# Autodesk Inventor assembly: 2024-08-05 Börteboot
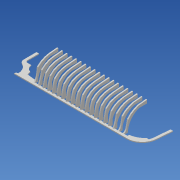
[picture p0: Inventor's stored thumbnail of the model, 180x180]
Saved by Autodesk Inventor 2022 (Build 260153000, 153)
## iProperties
Created: 2024-08
Part Number: 2024-08-05 Börteboot
Document SubType Name: Assembly
Designer: i3meg
Author: i3meg
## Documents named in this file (3)
- E:\Daten Autodesk Inventor 2022\Daten 3D Druck Vorlagen\3D Druck Vorlagen\Modellbau Fahrzeuge Schiffe\U-Boote und Schiffe\Schiffe Volker\Börte Boot\Inventor\2024-08-05 Börteboot 001.iam
- E:\Daten Autodesk Inventor 2022\Daten 3D Druck Vorlagen\3D Druck Vorlagen\Modellbau Fahrzeuge Schiffe\U-Boote und Schiffe\Schiffe Volker\Börte Boot\Inventor\2024-08-05 Börteboot Kiel 001.ipt
- E:\Daten Autodesk Inventor 2022\Daten 3D Druck Vorlagen\3D Druck Vorlagen\Modellbau Fahrzeuge Schiffe\U-Boote und Schiffe\Schiffe Volker\Börte Boot\Inventor\2024-08-05 Börteboot Spanten 001.ipt
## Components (2 placed, 2 different names)
1. 2024-08-05 Börteboot Kiel 001:1 — Passend:2, Fluchtend:1, Passend:3
2. 2024-08-05 Börteboot Spanten 001:1 — Passend:2, Fluchtend:1, Passend:3
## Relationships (3: Mate 2, Flush 1)
- Passend:2 [Mate]: 2024-08-05 Börteboot Kiel 001:1 ↔ 2024-08-05 Börteboot Spanten 001:1
- Fluchtend:1 [Flush]: 2024-08-05 Börteboot Kiel 001:1 ↔ 2024-08-05 Börteboot Spanten 001:1
- Passend:3 [Mate]: 2024-08-05 Börteboot Kiel 001:1 ↔ 2024-08-05 Börteboot Spanten 001:1
